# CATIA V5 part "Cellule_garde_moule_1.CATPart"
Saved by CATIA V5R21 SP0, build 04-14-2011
Part number: Moule_cellule_garde.1
Bounding box of the stored display mesh (mm): x -18 to 18, y -72 to 72, z -11 to 0
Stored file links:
  C:\Users\zerma\Pictures\Stage Stomate\Moule\Cellule_garde_moule_1.CATPart
  Product1.CATProduct
  C:\Users\zerma\Pictures\Moule\Moule_v1.CATPart
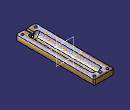
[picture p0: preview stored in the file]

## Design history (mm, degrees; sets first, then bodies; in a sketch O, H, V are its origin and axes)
Body1 (main body)
  Sketch1 on yz-plane, origin (0, 0, 0), H (0, 1, 0), V (0, 0, 1)
    line L1 (-95, -12.5) -> (95, -12.5)
    point P1 (-95, -12.5)
    line L2 (-100, -15) -> (100, -15)
    point P3 (-100, -15)
    line L3 (-95, -12.5) -> (-95, 0)
    point P5 (-95, 0)
    line L4 (-100, -15) -> (-100, 0)
    point P6 (-100, 0)
    line L5 (-95, 0) -> (-100, 0)
    point P7 (100, 0)
    point P8 (100, -15)
    line L6 (100, -15) -> (100, 0)
    point P9 (95, 0)
    line L7 (95, 0) -> (100, 0)
    point P10 (95, -12.5)
    line L8 (95, -12.5) -> (95, 0)
    distance L1 H = 12.5
    distance L1 L2 = 2.5
    length L4 = 15
    distance L4 L3 = 5
    length L1 = 190
    length L2 = 200
    distance V L3 = 95
    horizontal: L1 H, L2 H, L5 H
    vertical: L3 V, L4 V
    symmetry: P6 P7 V, P3 P8 V, L4 L6 V, P5 P9 V, L5 L7 V, P1 P10 V, L3 L8 V
  Shaft1: profile Sketch1, axis Sketch1.H, angle 360
  Sketch2 on face of Shaft1 from Sketch1.L4, origin (0, -100, 0), H (1, 0, 0), V (0, 0, 1)
    line L1 (-10, 2.5) -> (10, 2.5)
    line L2 (10, 2.5) -> (10, -2.5)
    line L3 (10, -2.5) -> (-10, -2.5)
    line L4 (-10, -2.5) -> (-10, 2.5)
    length L2 = 5
    length L1 = 20
    horizontal: L1 H, L3 H
    vertical: L2 V, L4 V
    symmetry: L3 L1 H, L4 L2 V
  Pad1: profile Sketch2, direction (0, -1, 0), length 15
  Sketch3 on face of Pad1 from Sketch2.L1, origin (0, 0, 2.5), H (1, 0, 0), V (0, 1, 0)
    circle A1 centre (0, -107.5) radius 2.5
    point P1 (0, -107.5)
    reference intersected line E1 (14.7902, -100) -> (-14.7902, -100) from face of Shaft1 from Sketch1.L4
    radius A1 = 2.5
    distance P1 E1 = 7.5
    coincidence: P1 V
  Pocket1: profile Sketch3, direction (0, 0, -1), length 5, mirrored extent
  Fillet1: radius 2, on edge [face of Pad1 from Sketch2.L4 | end face of Pad1]; edge [face of Pad1 from Sketch2.L1 | end face of Pad1]; edge [face of Pad1 from Sketch2.L3 | end face of Pad1]; edge [face of Pad1 from Sketch2.L2 | end face of Pad1]; edge [face of Pad1 from Sketch2.L2 | face of Pad1 from Sketch2.L3]; edge [face of Shaft1 from Sketch1.L4 | face of Pad1 from Sketch2.L3]; edge [face of Pad1 from Sketch2.L3 | face of Pad1 from Sketch2.L4]; edge [face of Pocket1 from Sketch3.A1 | face of Pad1 from Sketch2.L3]; edge [face of Pad1 from Sketch2.L4 | face of Pad1 from Sketch2.L1]; edge [face of Pad1 from Sketch2.L1 | face of Pad1 from Sketch2.L2]; edge [face of Shaft1 from Sketch1.L4 | face of Pad1 from Sketch2.L1]; edge [face of Shaft1 from Sketch1.L4 | face of Pad1 from Sketch2.L4]; edge [face of Shaft1 from Sketch1.L4 | face of Pad1 from Sketch2.L2]; face of Pad1 from Sketch2.L1
  Mirror1: of Pad1, Pocket1, Fillet1, about zx-plane
  Fillet2: radius 4, on edge [face of Shaft1 from Sketch1.L2 | face of Shaft1 from Sketch1.L6]; edge [face of Shaft1 from Sketch1.L4 | face of Shaft1 from Sketch1.L2]
Body2
  Sketch4 on xy-plane, origin (0, 0, 0), H (1, 0, 0), V (0, 1, 0)
    line L1 (18, 72) -> (18, -72)
    line L2 (18, -72) -> (-18, -72)
    line L3 (-18, -72) -> (-18, 72)
    line L4 (-18, 72) -> (18, 72)
    length L4 = 36
    length L1 = 144
    vertical: L1 V, L3 V
    horizontal: L2 H, L4 H
    symmetry: L2 L4 H, L1 L3 V
  Pad2: profile Sketch4, direction (0, 0, -1), length 11
  Body3
    Sketch5 on yz-plane, origin (0, 0, 0), H (0, 1, 0), V (0, 0, 1)
      line L1 (-55, -4.5) -> (55, -4.5)
      point P1 (-55, -4.5)
      point P2 (55, -4.5)
      line L2 (-60, -9) -> (60, -9)
      point P3 (-60, -9)
      point P4 (60, -9)
      line L3 (-55, -4.5) -> (-55, 0)
      point P5 (-55, 0)
      line L4 (-60, -9) -> (-60, -2.5)
      point P6 (-60, -2.5)
      point P7 (60, -2.5)
      point P8 (60, -9)
      line L5 (60, -9) -> (60, -2.5)
      point P9 (55, 0)
      point P10 (55, -4.5)
      line L6 (55, -4.5) -> (55, 0)
      line L7 (-60, -2.5) -> (-72, -2.5)
      line L8 (-72, -2.5) -> (-72, 0)
      line L9 (-72, 0) -> (-55, 0)
      point P13 (-55, 0)
      line L10 (60, -2.5) -> (67, -2.5)
      line L11 (67, -2.5) -> (67, 0)
      line L12 (67, 0) -> (55, 0)
      distance L1 H = 4.5
      distance L1 L2 = 4.5
      length L4 = 6.5
      distance L4 L3 = 5
      distance V L3 = 55
      length L9 = 17
      length L12 = 12
      length L11 = 2.5
      horizontal: L1 H, L2 H, L7 H, L9 H, L10 H, L12 H
      vertical: L3 V, L4 V, L8 V, L11 V
      symmetry: P6 P7 V, P3 P8 V, L4 L5 V, P5 P9 V, P1 P10 V, L3 L6 V
      coincidence: P13 P5, P2 P10, P4 P8
    Shaft2: profile Sketch5, axis Sketch5.H, angle 360
  Remove1: tool Body3
  Sketch6 on face of Shaft2 from Sketch5.L6, origin (0, 55, 0), H (-1, 0, 0), V (0, 0, 1)
    circle A1 centre (0, 0) radius 4.5
    reference projected circle E1 centre (0, 0) radius 4.5 from edge [face of Shaft2 from Sketch5.L1 | face of Shaft2 from Sketch5.L6]
    reference projected circle E2 centre (0, 0) radius 4.5 from edge [face of Shaft2 from Sketch5.L1 | face of Shaft2 from Sketch5.L6]
    coincidence: A1 E1
    concentricity: A1 E2
  Pocket2: profile Sketch6, direction (0, -1, 0), up to face of Shaft2 from Sketch5.L3
  Sketch7 on end face of Pad2, origin (0, 0, -11), H (1, 0, 0), V (0, -1, 0)
    circle A1 centre (12, 66) radius 2.25
    point P1 (12, 66)
    circle A2 centre (12, -66) radius 2.25
    circle A3 centre (-12, 66) radius 2.25
    circle A4 centre (-12, -66) radius 2.25
    reference projected line E1 (18, 95) -> (18, -95) from edge [end face of Pad2 | face of Pad2 from Sketch4.L1]
    reference projected line E2 (-20, 72) -> (20, 72) from edge [end face of Pad2 | face of Pad2 from Sketch4.L2]
    radius A1 = 2.25
    distance P1 E1 = 6
    distance P1 E2 = 6
    symmetry: A1 A2 H, A1 A3 V, A3 A4 H
  Pocket3: profile Sketch7, direction (0, 0, 1), length 50, mirrored extent
  Sketch8 on end face of Pad2, origin (0, 0, -11), H (1, 0, 0), V (0, -1, 0)
    circle A1 centre (12, 66) radius 3.5
    reference projected circle E1 centre (12, 66) radius 2.25 from edge [face of Pocket3 from Sketch7.A1 | end face of Pad2]
    circle A2 centre (12, -66) radius 3.5
    circle A3 centre (-12, 66) radius 3.5
    circle A4 centre (-12, -66) radius 3.5
    radius A1 = 3.5
    concentricity: A1 E1
    symmetry: A1 A2 H, A1 A3 V, A3 A4 H
  Pocket4: profile Sketch8, direction (0, 0, 1), length 8
  Fillet3: radius 4, on edge [face of Shaft2 from Sketch5.L5 | face of Shaft2 from Sketch5.L2]
  Fillet4: radius 4, on edge [face of Shaft2 from Sketch5.L2 | face of Shaft2 from Sketch5.L4]
  DatumCurve1
  Sketch9 on start face of Pad2, origin (0, 0, 0), H (1, 0, 0), V (0, 1, 0)
    circle A1 centre (0, 54) radius 1
    point P1 (0, 54)
    reference projected line E1 (28, 118) -> (28, -118) from edge of DatumCurve1
    reference projected line E2 (20, 72) -> (-20, 72) from edge [face of Pad2 from Sketch4.L4 | start face of Pad2]
    circle A2 centre (0, -54) radius 1
    radius A1 = 1
    distance P1 E1 = 28
    distance P1 E2 = 18
    symmetry: A1 A2 H
  Pocket5: profile Sketch9, direction (0, 0, -1), through (limit type 6)
  Sketch10 on face of Shaft2 from Sketch5.L4, origin (0, -60, 0), H (-1, 0, 0), V (0, 0, 1)
    circle A1 centre (0, -6) radius 1.75
    point P1 (0, -6)
    reference projected line E1 (9, 0) -> (2.5, 0) from edge [start face of Pad2 | face of Shaft2 from Sketch5.L4]
    radius A1 = 1.75
    distance P1 E1 = 6
  Pocket6: profile Sketch10, direction (0, -1, 0), length 15, mirrored extent
  Chamfer1: length 2, angle 45, on edge [face of Pad2 from Sketch4.L2 | face of Pad2 from Sketch4.L1]; edge [end face of Pad2 | face of Pad2 from Sketch4.L1]; edge [face of Pad2 from Sketch4.L1 | face of Pad2 from Sketch4.L4]; edge [end face of Pad2 | face of Pad2 from Sketch4.L4]; edge [face of Pad2 from Sketch4.L4 | face of Pad2 from Sketch4.L3]; edge [end face of Pad2 | face of Pad2 from Sketch4.L2]; edge [end face of Pad2 | face of Pad2 from Sketch4.L3]; edge [face of Pad2 from Sketch4.L3 | face of Pad2 from Sketch4.L2]
  CLDGeom1 "Maillage.1"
